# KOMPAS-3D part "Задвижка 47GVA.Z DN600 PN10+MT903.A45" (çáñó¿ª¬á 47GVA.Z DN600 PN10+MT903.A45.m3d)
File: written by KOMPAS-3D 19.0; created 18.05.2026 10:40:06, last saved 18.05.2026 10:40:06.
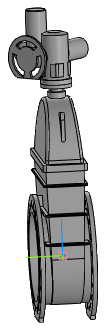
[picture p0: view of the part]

Document properties: Автор: Энергия; Полное имя файла: ..\Задвижка 47GVA.Z DN350_DN1200+MT903.A\Задвижка 47GVA.Z DN600 PN10+MT903.A45.a3d

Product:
- Part/product: Задвижка 47GVA.Z DN600 PN10+MT903.A45
    Масса: 1625.24
  - Body: Электропривод МТ903.А45 без блока управления
      Масса: 175.721
  - Body: Задвижка 47GVA.Z DN600 PN10 без исполнит. мех.
      Масса: 1449.52

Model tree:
1. Операция без истории:1
2. Операция без истории:2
